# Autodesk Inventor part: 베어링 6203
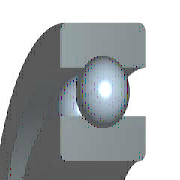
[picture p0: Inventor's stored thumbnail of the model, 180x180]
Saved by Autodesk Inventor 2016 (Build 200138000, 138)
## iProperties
IsCustomPart: 1
Created: 2012-02
Part Number: 베어링 6203
Material: 강철, 연강
Description: 깊은 그루브 볼 베어링
Document SubType Name: Modeling
Standard: KS B 2023
Designer: mduedu
Standards Organization: KS
Language: ko-KR
Size Designation: 6203 - 17 x 40 x 12
Categories: <MemberInstance><Categories><Category DisplayName="샤프트 부품" InternalName="7f7aeb1f-a693-4053-b835-cee3144e0d98" Mnemonic="SHFT"><Category DisplayName="베어링" Inter
Density: 1 g/cm^3
Appearance: 노란색
Author: mduedu
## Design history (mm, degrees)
sketch "스케치" dims "d0" = 5.98 (= -0.26 x WD + 0.26 x BD)
  geometry: L1 (3.01, 14.25)-(8.99, 14.25); L2 (6, 14.25)-(6, 11.26); L3 (6, 14.25)-(6, 17.24); L4 (3.778, 12.249)-(0, 12.249); L5 (0, 8.5)-(12, 8.5); L6 (3.778, 16.251)-(0, 16.251); L7 (0, 20)-(12, 20); L8 (12, 8.5)-(12, 12.249); L9 (8.222, 12.249)-(12, 12.249); L10 (8.222, 16.251)-(12, 16.251); L11 (12, 20)-(12, 16.251); L12 (-1.4, 0)-(8.4, 0) reference; L13 (0, -0.3)-(0, 5.3) reference
  constraints: 22 end point, 4 point on line, 2 collinear, 2 perpendicular, 2 symmetric about line, 1 midpoint, 1 parallel, 14 other
  dimensions: "d9" = 17 diameter of L5 L12 (= WD); "d11" = 40 diameter of L7 L12 (= BD); "d12" = 12 distance between parallel lines of L8 L13 (= KB); "d13" = 24.498 diameter of L9 L12 (= 0.326 x BD + 0.674 x WD)
revolve "본체" stored, may be unused: angle "d6" = 90 deg
revolve "볼" stored, may be unused: angle "d7" = 90 deg
pattern_circular "IDS_ARRAYBALL[SIMPL:T]" dims angle "d3" = 360 deg
body "Solid1"
fillet "모깎기1" dims "d1" = 0.6 (= KRS)
other parameters: "WD" = 17 [user parameter; used in 5 equation terms], "BD" = 40 [user parameter; used in 5 equation terms], "KB" = 12 [user parameter; used in 1 equation term], "KRS" = 0.6 [user parameter; used in 1 equation term], "d4" = 0, "d5" = 0, "d8" = 0, "d14" = 0, "d15" = 0, "BBA" = 0 [user parameter], "BC0" = 4750000 [user parameter], "BC" = 9560000 [user parameter], "WR" = 8.5 (= 0.5 x WD) [user parameter]
